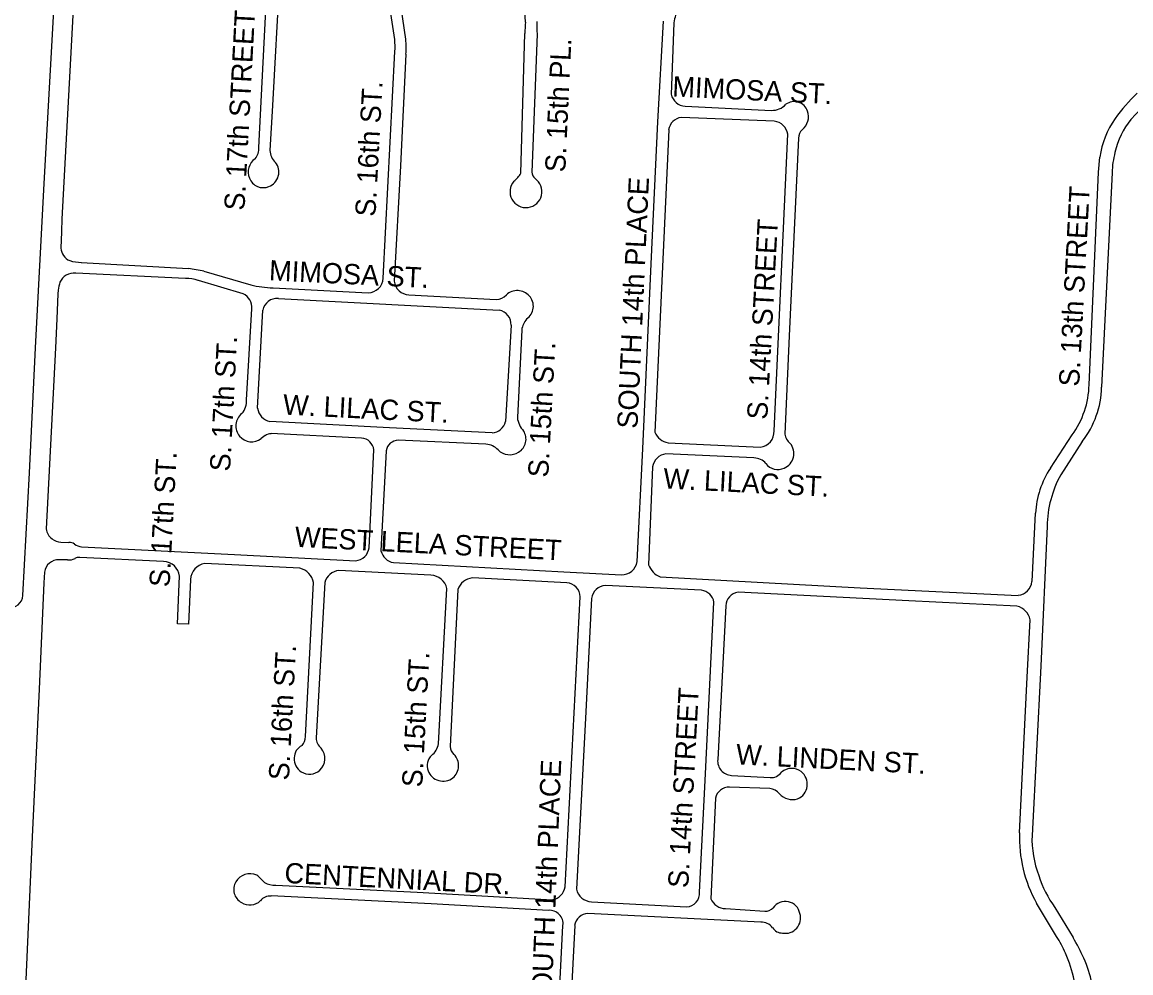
# Model space of a CAD drawing. Extents: x 0 to 712119, y 0 to 761125.
# Drawn here: x 680612 to 683343, y 727282 to 729625 of the extents above; entities that cross this region are included whole.
import ezdxf

# ---------------------------------------------------------------- set-up
doc = ezdxf.new("R2010")
doc.units = 0
doc.layers.add('PAVED ROADS', color=7, linetype='Continuous')
doc.layers.add('street names', color=7, linetype='Continuous')

msp = doc.modelspace()

# ---------------------------------------------------------------- linework, layer by layer
at = {"layer": 'PAVED ROADS'}
for points in [[(680614, 728212), (680630, 728514.5), (680644.7, 728822.1), (680665.9, 729227.4), (680690.2, 729654.1), (680694.9, 729745.5), (680694.5, 729768)], [(680743, 729764.7), (680728.5, 729489.2), (680710.4, 729155.1)], [(681195.3, 729316.6), (681216.3, 729736)], [(681245.5, 729734.3), (681228.7, 729419.7), (681222.3, 729309)], [(681530, 729582.6), (681511.1, 729705.4), (681509.4, 729723.7)], [(681537.6, 729711.8), (681556.5, 729582.8)], [(681851.3, 729625.1), (681850.2, 729654.2)], [(682126.6, 728295.6), (682140.9, 728573.2), (682161.5, 729029.9), (682177.7, 729379.6), (682191.4, 729627.5)], [(682217.4, 729623.7), (682210.4, 729447.2)], [(681840, 729252.8), (681850.3, 729597.2)], [(681880.2, 729595.6), (681867.4, 729255.4)], [(681501.3, 728994), (681530.2, 729553.2)], [(681557.1, 729546.4), (681543.7, 729270.9), (681528.6, 728986.8)], [(682245, 729417.8), (682457.7, 729407.7)], [(683367.4, 729411.9), (683342.6, 729385.5)], [(682464.3, 729380.8), (682235.6, 729390.3)], [(682204.4, 729359.4), (682170.2, 728614.6)], [(682463.9, 728617.7), (682497.7, 729348.9), (682497.7, 729348.9)], [(682524.1, 729339.5), (682501.2, 728851.9), (682490.1, 728609.6)], [(683239.9, 728731.4), (683262.7, 729255.6), (683266.3, 729292.4)], [(681185.8, 729288.5), (681185.8, 729288.5)], [(681875.2, 729239.9), (681875.2, 729239.9)], [(683296.5, 729254.3), (683270.7, 728725.7)], [(680708.7, 729108.1), (680707.5, 729068.2)], [(680757.7, 729033.1), (681021.3, 729017.8)], [(681014.4, 728993.6), (680743.9, 729006.3)], [(681059.8, 729011.4), (681175.1, 728978)], [(680700.3, 728964.4), (680700.1, 728955.6), (680697.5, 728894.1), (680694.3, 728822.5), (680671.5, 728376)], [(680704.9, 728984.1), (680704.9, 728984.1)], [(681156.7, 728955.9), (681045.9, 728988.6)], [(681229.8, 728970.5), (681464.1, 728957.9)], [(681243, 728943.8), (681786.8, 728915.1)], [(681564.4, 728953.1), (681779.8, 728941.7)], [(681164.8, 728694.6), (681177.5, 728919)], [(681192, 728674.1), (681204.6, 728915.2)], [(681816, 728878), (681802.4, 728641.3)], [(681842.5, 728866.8), (681831.6, 728650.6)], [(681769.3, 728613.1), (681517.1, 728625.4), (681222.3, 728640.6)], [(681447.7, 728600.1), (681225.1, 728611)], [(683144.4, 728526.2), (683198, 728607.8)], [(681210.9, 728606.1), (681200.5, 728598.8)], [(681754.4, 728584.7), (681538.4, 728594.7)], [(682202.9, 728588.7), (682429.5, 728577.6)], [(683223, 728591.6), (683169.9, 728509.3)], [(681466.6, 728329.7), (681478.1, 728571)], [(681508.4, 728569), (681495.7, 728322)], [(682414.4, 728551), (682197.4, 728561.1)], [(682164.7, 728529.2), (682154.9, 728287.8)], [(683099.2, 728246.6), (683107.8, 728414.6)], [(683136.3, 728383), (683121.3, 728037.7), (683099.3, 727621)], [(680707.5, 728343.6), (680727.2, 728342.8)], [(680758.1, 728332), (681135.2, 728312.8), (681433.6, 728297.6)], [(680724, 728299.9), (680703.4, 728300.1)], [(680960.4, 728295.8), (680754, 728306)], [(681296.2, 728279.2), (681061.5, 728290.9)], [(681526.7, 728293.1), (681946.4, 728270.4), (682087.8, 728263.3)], [(680667, 728269.5), (680665.5, 728243.5), (680654, 727981), (680636.5, 727617), (680620, 727246.5)], [(681026.6, 728251.5), (681021.3, 728141.1), (680994.2, 728142.6), (680999.5, 728259.6)], [(681618.6, 728262.1), (681391.9, 728273.8)], [(681953.5, 728243.6), (681720.8, 728255.5)], [(682183.1, 728257.8), (682676.2, 728231), (683065.5, 728212.5)], [(681309.9, 727864.4), (681329.2, 728243.8)], [(681357.2, 728244.3), (681336.5, 727861.2)], [(681637.7, 727846.4), (681658.3, 728229.4)], [(681685.3, 728226.8), (681666.2, 727840)], [(682285.2, 728225), (682048.5, 728236.7)], [(681949.1, 727494), (681986.7, 728208.8)], [(682014.3, 728204.8), (681999.8, 727909.6), (681977.2, 727488.4)], [(682014.3, 728204.8), (682014.3, 728204.8)], [(683062.2, 728185.5), (682796.2, 728198.9), (682585.9, 728210), (682375.1, 728220.5)], [(682280.1, 727480.7), (682294.2, 727756.5), (682315.8, 728195.7)], [(682344.8, 728186.8), (682325, 727807.8)], [(683068.8, 727627.3), (683087.6, 728010.7), (683094.5, 728152.3)], [(682359.1, 727768.6), (682453.9, 727763.7)], [(682453.5, 727736.2), (682354.1, 727740.1)], [(682319.5, 727712.5), (682308.2, 727464.7)], [(681236.6, 727498.6), (681584.9, 727480.8), (681918.6, 727462.4)], [(681908, 727436.1), (681619.2, 727452.1), (681472.2, 727459.3), (681225.2, 727471.5)], [(682014.1, 727457.5), (682248.6, 727444.9)], [(682344.6, 727440.3), (682441, 727433.9)], [(683159.5, 727371.9), (683110.4, 727454.1)], [(683155.6, 727443.2), (683200.5, 727369)], [(682431.2, 727407.4), (682005.6, 727428.7)], [(681935, 727217.4), (681944, 727398.9)], [(681972.8, 727399), (681963, 727210.5)]]:
    msp.add_lwpolyline(points, dxfattribs=at)
for centre, radius, start, end in [((682409.3, 729589.8), 559.1, 176.377, 179.244), ((682128, 729617.5), 248.7, 177.8614, 185.0532), ((682291.2, 729617.3), 74.1, 160.3989, 175.0074), ((681202.1, 729565.4), 328.3, 357.8659, 3.0004), ((681432.1, 729562.5), 126.1, 352.6556, 9.2546), ((682247.3, 729455.6), 37.8, 192.7153, 266.5082), ((682513.3, 729393.9), 35.4, 20.2218, 125.4663), ((683680.8, 729114.1), 465.7, 133.7991, 144.0711), ((682458.9, 729453.2), 45.5, 268.4765, 318.0197), ((682506.5, 729392.6), 42.3, 309.5265, 18.6174), ((682239.8, 729354.8), 35.8, 96.8209, 172.6249), ((682461, 729344), 37, 7.7244, 84.8638), ((683485.3, 729261), 221.2, 145.1685, 171.8296), ((683505.3, 729256.8), 207.5, 141.6549, 166.7847), ((682549.4, 729340.4), 25.3, 129.32, 182.0852), ((681154.7, 729314.7), 40.6, 319.8187, 2.6178), ((681263.9, 729310.3), 41.6, 181.7491, 227.4671), ((683551.4, 729243.4), 255.3, 166.229, 171.8923), ((681208.7, 729255.8), 40, 125.0867, 202.9021), ((681206.2, 729255.7), 38, 290.6979, 39.0239), ((683531.2, 729247.3), 234.9, 172.1393, 178.2965), ((681205.6, 729253.6), 36.3, 201.5664, 292.7037), ((681852.9, 729207.4), 39.3, 139.4746, 55.5159), ((681792.8, 729276), 52.5, 305.0876, 333.8239), ((681886.9, 729255.5), 19.5, 180.1057, 233.0471), ((680978.2, 729136.7), 268.4, 176.0748, 180.4466), ((681911.7, 729070.9), 1203.6, 176.963, 178.2294), ((680742, 729069.5), 34.5, 182.1881, 247.9576), ((680757.4, 729125.1), 92, 252.0454, 270.2026), ((680983.1, 728671.8), 348.1, 77.2677, 83.6934), ((680738.7, 728970), 36.6, 81.8176, 157.3547), ((681011.7, 728873.8), 119.8, 73.4392, 88.7414), ((681463, 728996.2), 38.3, 271.5354, 356.6835), ((681081.8, 728885.8), 389.5, 165.3746, 168.3562), ((681230.4, 729177.9), 207.4, 254.523, 269.8246), ((681566, 728990.7), 37.7, 185.9561, 267.5881), ((681831.6, 728924.1), 39.6, 41.9541, 133.2097), ((681139.6, 728922), 38, 355.4001, 63.2536), ((681239.1, 728909), 35, 83.6124, 169.7797), ((681778.3, 728977.5), 35.9, 272.4582, 316.8522), ((681833, 728924.9), 38, 304.4509, 42.5103), ((681780.8, 728880.3), 35.3, 356.3349, 80.0968), ((681891.5, 728860.8), 49.4, 138.5119, 173.1185), ((683020.5, 728736.7), 219.4, 323.9973, 358.6093), ((683043.1, 728731.1), 227.7, 322.2017, 358.6325), ((681118.4, 728691.5), 46.5, 318.199, 3.8278), ((681231.2, 728679.2), 39.6, 187.3742, 256.9587), ((681176.5, 728630), 38.4, 127.5955, 220.9962), ((681767.1, 728649.1), 36.1, 273.4292, 347.4145), ((681889.1, 728657), 57.8, 186.4525, 223.211), ((681225.7, 728586), 24.9, 91.3918, 126.4029), ((681816.1, 728597.2), 36.9, 300.4034, 33.3508), ((682208.8, 728629.7), 41.4, 201.4233, 261.7764), ((682425.4, 728615.9), 38.6, 276.1248, 2.7095), ((682527.9, 728616.7), 38.4, 190.5695, 231.1486), ((681177.2, 728629.4), 38.5, 219.7114, 307.3395), ((681446, 728567.9), 32.2, 5.5049, 87.098), ((681538.8, 728563.9), 30.8, 90.7359, 170.4521), ((681753.6, 728544.2), 40.5, 40.8576, 88.9386), ((682473.2, 728562.2), 39.3, 293.6534, 38.719), ((681812.9, 728599.9), 40.9, 225.5058, 302.2728), ((682202.3, 728523.5), 38, 97.4486, 171.3179), ((682414.5, 728511.9), 39.1, 41.4482, 90.048), ((682473.1, 728558.3), 35.8, 214.9591, 296.3654), ((683334.8, 728401.8), 227.4, 146.8287, 176.7682), ((683407.3, 728378.6), 271, 151.1525, 179.0576), ((680702.6, 728378.1), 31.2, 183.8268, 236.686), ((680713.3, 728391.8), 48.6, 235.0433, 263.1429), ((680729.7, 728327.1), 15.9, 45.2022, 99.0865), ((680765.5, 728378.4), 46.9, 238.3798, 260.9908), ((681429.8, 728334.5), 37.1, 275.8545, 352.5422), ((681533.2, 728331.2), 38.6, 193.7952, 260.2652), ((680702.1, 728264.6), 35.5, 87.8845, 172.1057), ((680727.8, 728327.9), 28.3, 262.333, 300.4631), ((680751.8, 728286.3), 19.8, 83.8049, 119.37), ((680959.6, 728255.8), 40, 5.4617, 88.8806), ((681068.3, 728249.7), 41.8, 99.3174, 177.5137), ((682089.6, 728300.6), 37.3, 267.1613, 352.3459), ((682203.9, 728305.6), 52.1, 199.9487, 246.4756), ((681287.1, 728237.6), 42.5, 8.462, 77.7135), ((681397.1, 728232.4), 41.7, 97.281, 163.4631), ((681617.6, 728220.3), 41.7, 12.5022, 88.6303), ((681725.3, 728213.5), 42.2, 96.1895, 161.6047), ((681949.6, 728206.6), 37.2, 3.4084, 84.0117), ((682050.1, 728200.7), 36, 92.5032, 173.5356), ((683061.6, 728250.1), 37.7, 275.8564, 354.7178), ((680580.4, 728215.1), 33.7, 265.0058, 354.7596), ((682281.5, 728190.4), 34.7, 8.6697, 83.926), ((682380.8, 728184.8), 36.1, 99.0698, 176.862), ((683053.7, 728145), 41.4, 10.0656, 78.2243), ((681270.9, 727866.5), 39.1, 321.3716, 356.9088), ((681366, 727859.7), 29.6, 177.0487, 233.4852), ((681593.1, 727854.5), 45.3, 306.5924, 349.6768), ((681314.4, 727812.7), 32.2, 113.952, 181.748), ((681319.1, 727810.5), 38.7, 311.7068, 40.8646), ((681645.6, 727792.5), 36.1, 134.7241, 199.7831), ((681690.3, 727839.6), 24.2, 179.1443, 232.529), ((681647, 727792.8), 39.8, 310.8375, 43.9751), ((681319.2, 727808.8), 37, 175.5339, 237.8525), ((682360.9, 727804.6), 36, 174.9301, 267.1693), ((681319.4, 727809.6), 37.8, 238.15, 312.2823), ((681648.8, 727794.3), 39.8, 200.718, 307.4545), ((682457.8, 727792.8), 29.3, 262.3553, 326.8808), ((682507.3, 727748), 38.1, 51.8859, 130.974), ((682506.1, 727747), 39.6, 293.5809, 51.4171), ((682353.3, 727705.6), 34.5, 88.5792, 168.3773), ((682449.6, 727701), 35.4, 39.4589, 83.6799), ((682509.6, 727753.1), 44.1, 222.2034, 286.2062), ((683392.1, 727613.3), 323.6, 177.5083, 209.4683), ((683360.6, 727613.6), 261.5, 178.3879, 200.5895), ((681173.3, 727485.3), 41, 66.6183, 149.0474), ((681049, 727354.6), 219.3, 43.2832, 50.138), ((683382.7, 727607.5), 280.3, 197.8358, 215.8919), ((681169.3, 727487.6), 36.3, 148.9091, 241.8679), ((681232.3, 727544.9), 46.5, 239.3899, 275.2599), ((681911.4, 727499.9), 38.1, 280.9419, 351.1584), ((682015.4, 727496.4), 39, 191.9244, 268.081), ((681223.2, 727439.9), 31.6, 86.5084, 140.6835), ((682247.8, 727477.3), 32.4, 271.4452, 6.1587), ((682345.3, 727480.7), 40.3, 203.3461, 269.0572), ((681172.8, 727486.2), 36.9, 236.1124, 314.7626), ((681911.3, 727403.3), 32.9, 352.185, 95.7305), ((682441.1, 727462.8), 28.9, 269.8025, 315.304), ((682491.6, 727421.9), 36.3, 9.7318, 145.492), ((682007.6, 727393.4), 35.3, 93.2619, 170.8952), ((682431.7, 727371.7), 35.6, 37.4902, 90.7638), ((682491.8, 727416.9), 37.4, 259.163, 17.4559), ((682483.8, 727408.2), 28, 211.7474, 271.9895), ((682871, 727189.5), 341.4, 24.3694, 32.2991), ((682653.1, 727053.9), 631.6, 24.7261, 29.9272), ((682847, 727185.6), 364.9, 1.4666, 23.3663), ((682979.7, 727205.5), 271.5, 357.1174, 24.4948)]:
    msp.add_arc(centre, radius, start, end, dxfattribs=at)

# ---------------------------------------------------------------- texts
at = {"layer": 'street names'}
for s, rotation, p in [('S. 17th STREET', 86.9341, (681159.4, 729159.9)), ('S. 15th PL.', 87.3457, (681949.6, 729254.3)), ('MIMOSA ST.', 357.2196, (682212.5, 729442)), ('S. 16th ST.', 86.9341, (681482, 729144.9)), ('SOUTH 14th PLACE', 87.3457, (682127.4, 728622.4)), ('S. 13th STREET', 86.9341, (683215.2, 728726.1)), ('S. 14th STREET', 86.9341, (682447.1, 728644.6)), ('MIMOSA ST.', 357.2196, (681219.2, 728989)), ('S. 17th ST.', 86.9341, (681124, 728516.9)), ('S. 15th ST.', 86.9341, (681907.6, 728502.1)), ('W. LILAC ST.', 357.0768, (681253.3, 728658.2)), ('S. 17th ST.', 86.9341, (680974.9, 728231.8)), ('W. LILAC ST.', 357.0768, (682190.1, 728476.1)), ('WEST LELA STREET', 357.0768, (681282.3, 728332.2)), ('S. 16th ST.', 86.9341, (681268.9, 727755.6)), ('S. 15th ST.', 86.9341, (681597.2, 727738.5)), ('S. 14th STREET', 86.9341, (682252.4, 727490.1)), ('W. LINDEN ST.', 357.0768, (682369.2, 727796.2)), ('SOUTH 14th PLACE', 87.7031, (681915.1, 727186.7)), ('CENTENNIAL DR.', 357.0515, (681257.1, 727503.8))]:
    msp.add_text(s, height=50, rotation=rotation, dxfattribs=at).set_placement(p)

doc.saveas('drawing.dxf')
